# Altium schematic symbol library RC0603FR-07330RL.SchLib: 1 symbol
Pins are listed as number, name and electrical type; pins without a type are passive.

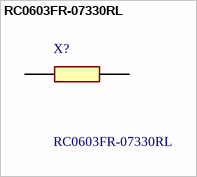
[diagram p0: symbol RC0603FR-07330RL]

## RC0603FR-07330RL
designator X?
YAGEO (PHYCOMP) - RC0603FR-07330RL - RES, THICK FILM, 330R, 1%, 0.1W, 0603; Manufacturer_Name: Yageo Group; Geometry.Height: 0.55mm
footprint RESC1608X55N
pins: 1, 2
